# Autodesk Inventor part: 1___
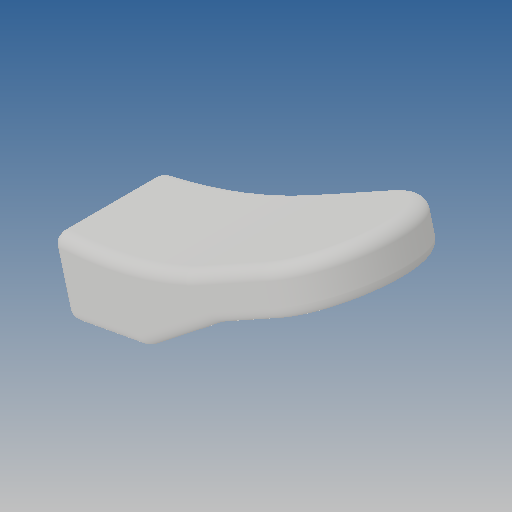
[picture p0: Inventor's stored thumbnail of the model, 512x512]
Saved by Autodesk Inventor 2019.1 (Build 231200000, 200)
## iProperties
Created: 2013-01
Part Number: 1___
Material: Ogólny
Document SubType Name: Modeling
Designer: CADENGINEERING4
Density: 1 g/cm^3
Appearance: Domyślna
Author: CADENGINEERING4
Revision Number: ÈÎºÎ
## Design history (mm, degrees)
feature "NONE"
node "Bryła1"
